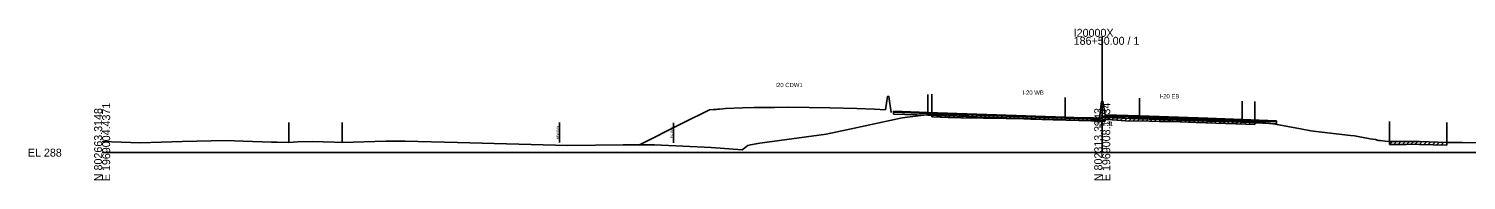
# Model space of a CAD drawing. Extents: x -4026 to 9638, y -10 to 19609.
# Drawn here: x 4974 to 5477, y 7990 to 8043 of the extents above; entities that cross this region are included whole.
import ezdxf

# ---------------------------------------------------------------- set-up
doc = ezdxf.new("R2010")
doc.units = 0
for name, color, linetype in [('Default', 7, 'Continuous'), ('RD_EX_Road', 7, 'Continuous'), ('RD_GPK_XS_Cell', 7, 'Continuous'), ('RD_PD_ALT1_TrvlWay', 7, 'Continuous'), ('RD_TX_Misc1', 7, 'Continuous'), ('RD_XS_Base', 7, 'Continuous'), ('RD_XS_ExGround', 7, 'Continuous'), ('RD_XS_ExPaveRet', 7, 'Continuous'), ('RD_XS_ExRW', 7, 'Continuous'), ('RD_XS_MedBWall', 7, 'Continuous'), ('RD_XS_NewRW', 7, 'Continuous'), ('RD_XS_Pave', 7, 'Continuous'), ('RD_XS_PaveOvlay', 7, 'Continuous'), ('RD_XS_TX_Elev_EX', 7, 'Continuous')]:
    doc.layers.add(name, color=color, linetype=linetype)

msp = doc.modelspace()

# ---------------------------------------------------------------- linework, layer by layer
at = {"layer": 'RD_EX_Road'}
for p, q in [((5290.32, 8020.52), (5290.32, 8013.52)), ((5403.35, 8017.89), (5403.35, 8010.89)), ((5065.28, 8010.6), (5065.28, 8003.6)), ((5083.96, 8010.6), (5083.96, 8003.6)), ((5450.52, 8010.88), (5450.52, 8003.88)), ((5470.55, 8010.59), (5470.55, 8003.59))]:
    msp.add_line(p, q, dxfattribs=at)
at = {"layer": 'RD_GPK_XS_Cell'}
for p, q in [((5350, 8000), (5350, 8040.57)), ((5000, 8000), (5350, 8000)), ((5350, 8000), (5700, 8000))]:
    msp.add_line(p, q, dxfattribs=at)
at = {"layer": 'RD_PD_ALT1_TrvlWay'}
for p, q in [((5289, 8020.34), (5289, 8013.34)), ((5337, 8019.36), (5337, 8012.36)), ((5363, 8019.08), (5363, 8012.08)), ((5399, 8018.02), (5399, 8011.02))]:
    msp.add_line(p, q, dxfattribs=at)
at = {"layer": 'RD_XS_Base'}
for points in [[(5277, 8014.15), (5277, 8013.48)], [(5289, 8013.74), (5277, 8014.15)], [(5277, 8013.48), (5289, 8013.07)], [(5337, 8012.11), (5313, 8012.93), (5289, 8013.74)], [(5289, 8013.74), (5289, 8013.07)], [(5289, 8013.74), (5289, 8013.74), (5289, 8013.07), (5289, 8013.07)], [(5289, 8013.07), (5313, 8012.26), (5337, 8011.44)], [(5337, 8011.44), (5337, 8012.11)], [(5349, 8011.64), (5337, 8012.11)], [(5337, 8011.44), (5349, 8010.97)], [(5349, 8010.97), (5349, 8011.64)], [(5351, 8012.25), (5351, 8012.92)], [(5351, 8012.92), (5363, 8012.5)], [(5363, 8011.83), (5351, 8012.25)], [(5363, 8011.83), (5363, 8012.5)], [(5363, 8012.5), (5387, 8011.69), (5399, 8011.28)], [(5399, 8010.61), (5387, 8011.02), (5363, 8011.83)], [(5399, 8011.28), (5399, 8011.28), (5399, 8010.61), (5399, 8010.61)], [(5399, 8010.61), (5399, 8011.28)], [(5399, 8011.28), (5411, 8010.8)], [(5411, 8010.13), (5399, 8010.61)], [(5411, 8010.8), (5411, 8010.13)]]:
    msp.add_lwpolyline(points, dxfattribs=at)
at = {"layer": 'RD_XS_ExGround'}
msp.add_lwpolyline([(5000, 8003.94), (5013.31, 8003.44), (5028.04, 8003.9), (5043.32, 8004.26), (5049.3, 8004), (5059.23, 8003.62), (5061.24, 8003.65), (5065.28, 8003.6), (5068.41, 8003.73), (5073.52, 8003.95), (5081.15, 8003.69), (5083.96, 8003.6), (5099.31, 8004.05), (5101.01, 8004.03), (5106.05, 8004.02), (5124.38, 8003.59), (5163.02, 8002.44), (5182.29, 8002.76), (5193.33, 8002.72), (5213.08, 8001.79), (5224.03, 8001), (5226.02, 8002.44), (5226.84, 8002.67), (5230.21, 8003.3), (5253.33, 8006.45), (5262.66, 8008.44), (5279.93, 8012.17), (5282.72, 8012.48), (5290.32, 8013.52), (5296.03, 8013.31), (5300.47, 8013.21), (5316.32, 8012.95), (5320.1, 8012.9), (5325, 8012.77), (5332.83, 8012.51), (5341.83, 8012.2), (5346.94, 8012.14), (5349.19, 8012.12), (5350, 8012.31), (5351.3, 8012.6), (5351.94, 8012.56), (5358.12, 8012.17), (5366.44, 8012.02), (5370.04, 8011.96), (5373.95, 8011.88), (5377.21, 8011.73), (5382.87, 8011.52), (5393.24, 8011.17), (5400.28, 8010.99), (5403.35, 8010.89), (5406.42, 8010.52), (5410.47, 8009.97), (5419.33, 8008.37), (5423.03, 8007.63), (5426.84, 8007.15), (5436.82, 8006.02), (5438.26, 8005.86), (5443.71, 8004.87), (5445.63, 8004.6), (5446.6, 8004.3), (5447.28, 8004.2), (5449.03, 8003.99), (5450.52, 8003.88), (5456.51, 8003.9), (5459.33, 8003.94), (5461.06, 8003.87), (5470.55, 8003.59), (5476.08, 8003.6), (5480.89, 8003.46)], dxfattribs=at)
at = {"layer": 'RD_XS_ExPaveRet'}
for p, q in [((5290.32, 8012.52), (5290.32, 8013.52)), ((5290.32, 8012.52), (5291.28, 8013.49)), ((5290.32, 8012.52), (5296.03, 8012.31)), ((5291.82, 8012.47), (5292.78, 8013.43)), ((5293.32, 8012.41), (5294.28, 8013.37)), ((5294.82, 8012.35), (5295.78, 8013.32)), ((5296.03, 8012.31), (5300.47, 8012.21)), ((5296.32, 8012.3), (5297.3, 8013.28)), ((5297.82, 8012.27), (5298.8, 8013.25)), ((5299.32, 8012.24), (5300.3, 8013.22)), ((5300.47, 8012.21), (5316.32, 8011.95)), ((5300.82, 8012.21), (5301.8, 8013.19)), ((5302.32, 8012.18), (5303.3, 8013.17)), ((5303.82, 8012.16), (5304.8, 8013.14)), ((5305.32, 8012.13), (5306.3, 8013.11)), ((5306.82, 8012.11), (5307.8, 8013.09)), ((5308.32, 8012.08), (5309.3, 8013.06)), ((5309.82, 8012.06), (5310.8, 8013.04)), ((5311.32, 8012.03), (5312.3, 8013.01)), ((5312.82, 8012), (5313.8, 8012.99)), ((5314.32, 8011.98), (5315.3, 8012.96)), ((5315.82, 8011.95), (5316.81, 8012.94)), ((5316.32, 8011.95), (5320.1, 8011.9)), ((5317.32, 8011.93), (5318.31, 8012.92)), ((5318.82, 8011.92), (5319.81, 8012.91)), ((5320.1, 8011.9), (5325, 8011.77)), ((5320.32, 8011.9), (5321.29, 8012.87)), ((5321.82, 8011.86), (5322.79, 8012.83)), ((5323.32, 8011.81), (5324.29, 8012.79)), ((5324.82, 8011.77), (5325.79, 8012.74)), ((5325, 8011.77), (5332.83, 8011.51)), ((5326.32, 8011.72), (5327.29, 8012.69)), ((5327.82, 8011.67), (5328.79, 8012.64)), ((5329.32, 8011.62), (5330.29, 8012.59)), ((5330.82, 8011.57), (5331.79, 8012.54)), ((5332.32, 8011.52), (5333.29, 8012.49)), ((5332.83, 8011.51), (5341.83, 8011.2)), ((5333.82, 8011.47), (5334.79, 8012.44)), ((5335.32, 8011.42), (5336.29, 8012.39)), ((5336.82, 8011.37), (5337.79, 8012.34)), ((5338.32, 8011.32), (5339.29, 8012.29)), ((5339.82, 8011.27), (5340.79, 8012.24)), ((5341.32, 8011.22), (5342.3, 8012.19)), ((5341.83, 8011.2), (5346.94, 8011.14)), ((5342.82, 8011.19), (5343.81, 8012.18)), ((5344.32, 8011.17), (5345.31, 8012.16)), ((5345.82, 8011.15), (5346.81, 8012.14)), ((5346.94, 8011.14), (5349.19, 8011.12)), ((5347.32, 8011.14), (5348.31, 8012.13)), ((5348.82, 8011.12), (5350, 8012.31)), ((5349.19, 8011.12), (5350, 8011.31)), ((5350, 8011.31), (5351.3, 8011.6)), ((5350.32, 8011.38), (5351.53, 8012.58)), ((5351.3, 8011.6), (5351.94, 8011.56)), ((5351.82, 8011.57), (5352.76, 8012.51)), ((5351.94, 8011.56), (5358.12, 8011.17)), ((5353.32, 8011.47), (5354.26, 8012.41)), ((5354.82, 8011.38), (5355.76, 8012.32)), ((5356.32, 8011.28), (5357.26, 8012.22)), ((5357.82, 8011.19), (5358.79, 8012.16)), ((5358.12, 8011.17), (5366.44, 8011.02)), ((5359.32, 8011.15), (5360.3, 8012.13)), ((5360.82, 8011.12), (5361.8, 8012.1)), ((5362.32, 8011.09), (5363.3, 8012.08)), ((5363.82, 8011.07), (5364.8, 8012.05)), ((5365.32, 8011.04), (5366.3, 8012.02)), ((5366.44, 8011.02), (5370.04, 8010.96)), ((5366.82, 8011.01), (5367.8, 8012)), ((5368.32, 8010.99), (5369.3, 8011.97)), ((5369.82, 8010.96), (5370.8, 8011.94)), ((5370.04, 8010.96), (5373.95, 8010.88)), ((5371.32, 8010.93), (5372.3, 8011.91)), ((5372.82, 8010.9), (5373.8, 8011.88)), ((5373.95, 8010.88), (5377.21, 8010.73)), ((5374.32, 8010.86), (5375.28, 8011.82)), ((5375.82, 8010.79), (5376.78, 8011.75)), ((5377.21, 8010.73), (5382.87, 8010.52)), ((5377.32, 8010.72), (5378.29, 8011.69)), ((5378.82, 8010.67), (5379.79, 8011.64)), ((5380.32, 8010.62), (5381.29, 8011.58)), ((5381.82, 8010.56), (5382.79, 8011.53)), ((5382.87, 8010.52), (5393.24, 8010.17)), ((5383.32, 8010.51), (5384.29, 8011.48)), ((5384.82, 8010.46), (5385.79, 8011.42)), ((5386.32, 8010.41), (5387.29, 8011.37)), ((5387.82, 8010.36), (5388.79, 8011.32)), ((5389.32, 8010.3), (5390.29, 8011.27)), ((5390.82, 8010.25), (5391.79, 8011.22)), ((5392.32, 8010.2), (5393.29, 8011.17)), ((5393.24, 8010.17), (5400.28, 8009.99)), ((5393.82, 8010.16), (5394.8, 8011.13)), ((5395.32, 8010.12), (5396.3, 8011.09)), ((5396.82, 8010.08), (5397.8, 8011.05)), ((5398.32, 8010.04), (5399.3, 8011.02)), ((5399.82, 8010), (5400.79, 8010.97)), ((5400.28, 8009.99), (5403.35, 8009.89)), ((5401.32, 8009.96), (5402.29, 8010.93)), ((5403.35, 8010.89), (5403.35, 8009.89)), ((5450.52, 8002.88), (5451.52, 8003.89)), ((5450.52, 8002.88), (5450.52, 8003.88)), ((5450.52, 8002.88), (5456.51, 8002.9)), ((5452.02, 8002.89), (5453.02, 8003.89)), ((5453.52, 8002.89), (5454.52, 8003.89)), ((5455.02, 8002.9), (5456.02, 8003.9)), ((5456.51, 8002.9), (5459.33, 8002.94)), ((5456.52, 8002.9), (5457.53, 8003.91)), ((5458.02, 8002.92), (5459.03, 8003.93)), ((5459.33, 8002.94), (5461.06, 8002.87)), ((5459.52, 8002.93), (5460.48, 8003.89)), ((5461.02, 8002.87), (5461.99, 8003.84)), ((5461.06, 8002.87), (5470.55, 8002.59)), ((5462.52, 8002.83), (5463.49, 8003.8)), ((5464.02, 8002.79), (5464.99, 8003.76)), ((5465.52, 8002.74), (5466.49, 8003.71)), ((5467.02, 8002.7), (5467.99, 8003.67)), ((5468.52, 8002.65), (5469.49, 8003.63)), ((5470.55, 8003.59), (5470.55, 8002.59))]:
    msp.add_line(p, q, dxfattribs=at)
at = {"layer": 'RD_XS_ExRW'}
msp.add_line((5200, 8003.41), (5200, 8010.41), dxfattribs=at)
at = {"layer": 'RD_XS_MedBWall'}
for points in [[(5349, 8011.97), (5349.75, 8017.92), (5350.25, 8017.92), (5351, 8013.25)], [(5349, 8010.97), (5349, 8011.97)], [(5351, 8010.97), (5349, 8010.97)], [(5351, 8013.25), (5351, 8010.97)]]:
    msp.add_lwpolyline(points, dxfattribs=at)
at = {"layer": 'RD_XS_NewRW'}
msp.add_line((5160.08, 8003.53), (5160.08, 8010.53), dxfattribs=at)
at = {"layer": 'RD_XS_Pave'}
for points in [[(5187.79, 8002.59), (5203.14, 8010.26), (5212.59, 8014.98), (5213.93, 8015.09), (5214.86, 8015.16), (5215.35, 8015.2), (5216.09, 8015.26), (5217.27, 8015.35), (5218.09, 8015.42), (5224.05, 8015.65), (5228.09, 8015.81), (5235.3, 8015.85), (5240.09, 8015.94), (5254.69, 8015.64), (5264.09, 8015.45), (5270.24, 8015.2), (5274.1, 8015.04), (5274.85, 8019.71), (5275.35, 8019.71), (5276.1, 8014.04)], [(5277, 8014.32), (5289, 8013.91)], [(5277, 8014.15), (5277, 8014.32)], [(5289, 8013.74), (5277, 8014.15)], [(5289, 8013.91), (5289, 8013.91), (5289, 8013.74), (5289, 8013.74)], [(5289, 8013.74), (5289, 8013.91)], [(5289, 8013.91), (5313, 8013.1), (5337, 8012.28)], [(5337, 8012.11), (5313, 8012.93), (5289, 8013.74)], [(5337, 8012.28), (5349, 8011.81)], [(5337, 8012.11), (5337, 8012.28)], [(5349, 8011.64), (5337, 8012.11)], [(5349, 8011.81), (5349, 8011.64)], [(5363, 8012.67), (5351, 8013.09)], [(5351, 8013.09), (5351, 8012.92)], [(5351, 8012.92), (5363, 8012.5)], [(5399, 8011.45), (5387, 8011.85), (5363, 8012.67)], [(5363, 8012.67), (5363, 8012.5)], [(5363, 8012.5), (5387, 8011.69), (5399, 8011.28)], [(5399, 8011.45), (5399, 8011.45), (5399, 8011.28), (5399, 8011.28)], [(5399, 8011.28), (5399, 8011.45)], [(5399, 8011.45), (5411, 8010.97)], [(5411, 8010.8), (5399, 8011.28)], [(5411, 8010.97), (5411, 8010.8)]]:
    msp.add_lwpolyline(points, dxfattribs=at)
at = {"layer": 'RD_XS_PaveOvlay'}
for points in [[(5277, 8014.49), (5289, 8014.08)], [(5277, 8014.32), (5277, 8014.49)], [(5289, 8013.91), (5277, 8014.32)], [(5289, 8014.08), (5313, 8013.27), (5337, 8012.45)], [(5289, 8013.91), (5289, 8014.08)], [(5289, 8014.08), (5289, 8014.08), (5289, 8013.91), (5289, 8013.91)], [(5337, 8012.28), (5313, 8013.1), (5289, 8013.91)], [(5337, 8012.45), (5337, 8012.28)], [(5337, 8012.45), (5349, 8011.97)], [(5349, 8011.81), (5337, 8012.28)], [(5349, 8011.97), (5349, 8011.81)], [(5363, 8012.84), (5351, 8013.25)], [(5351, 8013.25), (5351, 8013.09)], [(5351, 8013.09), (5363, 8012.67)], [(5399, 8011.61), (5387, 8012.02), (5363, 8012.84)], [(5363, 8012.84), (5363, 8012.67)], [(5363, 8012.67), (5387, 8011.85), (5399, 8011.45)], [(5399, 8011.45), (5399, 8011.61)], [(5399, 8011.61), (5411, 8011.13)], [(5399, 8011.61), (5399, 8011.61), (5399, 8011.45), (5399, 8011.45)], [(5411, 8010.97), (5399, 8011.45)], [(5411, 8011.13), (5411, 8010.97)]]:
    msp.add_lwpolyline(points, dxfattribs=at)

# ---------------------------------------------------------------- texts
at = {"layer": 'Default'}
msp.add_text('-', height=0.0001, dxfattribs=at).set_placement((5000, 8000))
at = {"layer": 'RD_GPK_XS_Cell'}
for s, p in [('186+50.00 / 1', (5340, 8037.77)), ('I20000X', (5340, 8040.57)), ('EL 288', (4974, 7998.6))]:
    msp.add_text(s, height=2.8, dxfattribs=at).set_placement(p)
for s, p in [('N 802663.3148', (5000, 7990)), ('E 1969004.4371', (5002.8, 7990)), ('N 802313.3343', (5350, 7990)), ('E 1969008.1334', (5352.8, 7990))]:
    msp.add_text(s, height=2.8, rotation=90, dxfattribs=at).set_placement(p)
at = {"layer": 'RD_TX_Misc1'}
for s, p in [('I20 CDW1', (5235.61, 8022.94)), ('I-20 WB', (5322.06, 8020.27)), ('I-20 EB', (5370.06, 8019.02))]:
    msp.add_text(s, height=1.5, dxfattribs=at).set_placement(p)
at = {"layer": 'RD_XS_ExRW'}
msp.add_text('EX. R/W ', height=0.75, rotation=90, dxfattribs=at).set_placement((5199.75, 8005.09))
at = {"layer": 'RD_XS_NewRW'}
msp.add_text('NEW R/W ', height=0.75, rotation=90, dxfattribs=at).set_placement((5159.83, 8004.67))
at = {"layer": 'RD_XS_TX_Elev_EX'}
msp.add_text('300.31', height=1.5, dxfattribs=at).set_placement((5347.52, 8009.31))

doc.saveas('drawing.dxf')
